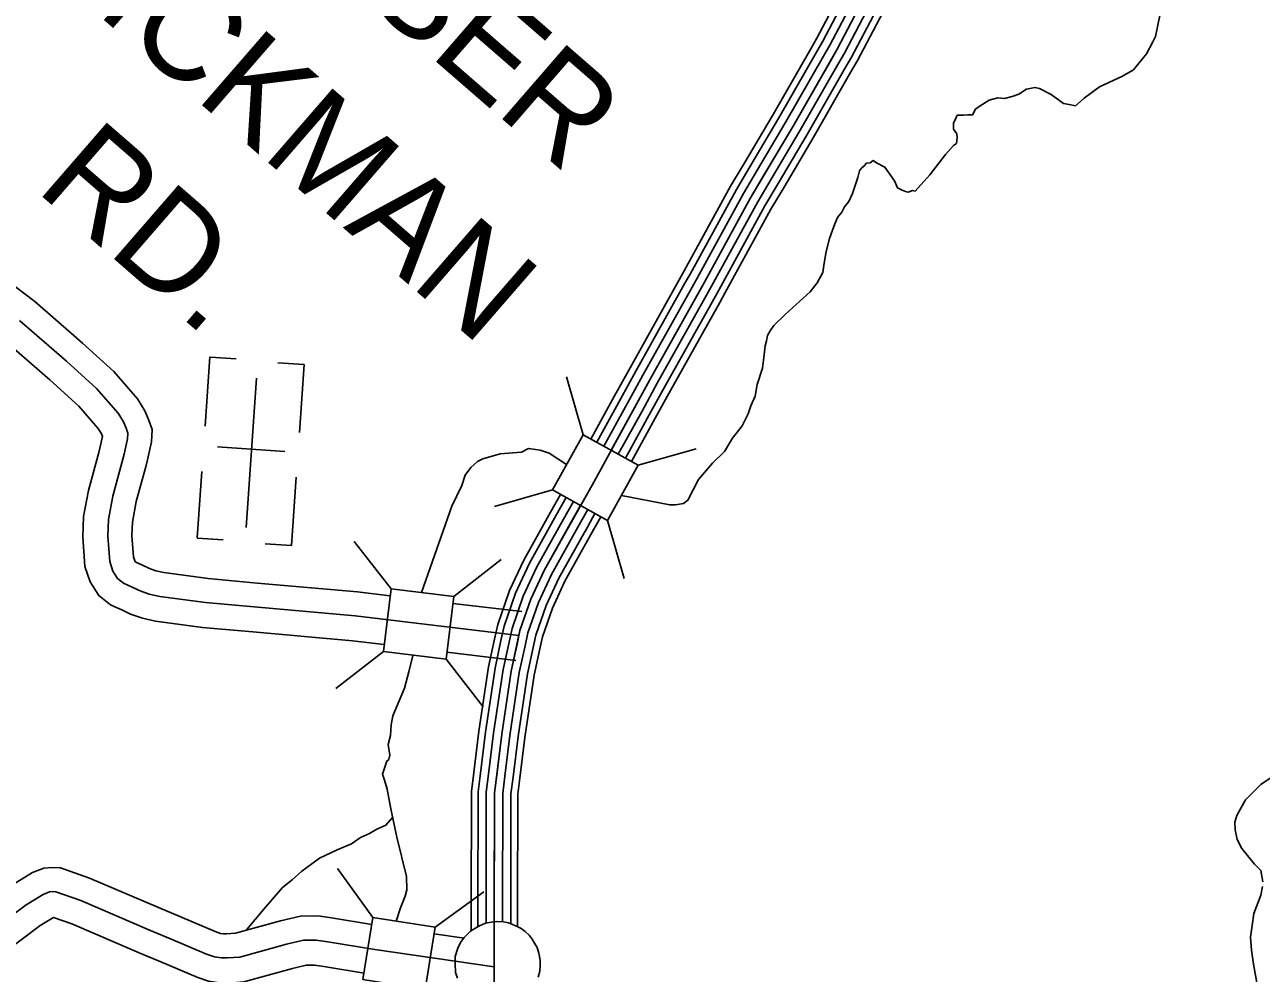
# Model space of a CAD drawing. Extents: x 1551132 to 1791609, y 378168 to 563823.
# Drawn here: x 1656295 to 1660954, y 405316 to 408888 of the extents above; entities that cross this region are included whole.
import ezdxf

# ---------------------------------------------------------------- set-up
doc = ezdxf.new("R2010")
doc.units = 0
for name, color, linetype in [('DESIGN - ROW - Right-of-Way and Easement Labels', 7, 'Continuous'), ('DESIGN - TRANSPORTATION - Text', 7, 'Continuous'), ('DESIGN - UTILITIES - Cable (Underground) with Text', 7, 'Continuous'), ('SURVEY - CENTERLINE - Preliminary Text', 7, 'Continuous'), ('SURVEY - DRAINAGE - Storm Sewer', 7, 'Continuous'), ('SURVEY - PROPERTY - Owners', 7, 'Continuous'), ('SURVEY - VEGETATION - Features with Text', 7, 'Continuous')]:
    doc.layers.add(name, color=color, linetype=linetype)

msp = doc.modelspace()

# ---------------------------------------------------------------- linework, layer by layer
at = {"layer": 'DESIGN - TRANSPORTATION - Text'}
for points in [[(1660555.903, 408843.7), (1660572.253, 408922.91), (1660572.453, 408974.97), (1660580.561, 409002.962), (1660584.686, 409036.988), (1660604.794, 409064.931), (1660624.918, 409098.881), (1660644.968, 409112.807), (1660663.009, 409124.741), (1660694.983, 409120.599), (1660714.983, 409120.507), (1660736.932, 409108.398), (1660762.882, 409098.273), (1660790.914, 409108.165), (1660824.972, 409124.032), (1660847.046, 409143.958), (1660867.121, 409165.9), (1660871.862, 409175.292)], [(1658543.482, 407114.353), (1658725.487, 407079.702), (1658746.978, 407080.086), (1658776.819, 407084.352), (1658793.868, 407097.144), (1658833.834, 407175.338), (1658886.066, 407237.173), (1658932.223, 407281.024), (1658962.406, 407330.951), (1658998.58, 407376.844), (1659020.755, 407422.803), (1659030.863, 407452.787), (1659047.004, 407488.763), (1659055.171, 407532.773), (1659075.404, 407594.758), (1659079.562, 407634.784), (1659085.728, 407678.81), (1659089.795, 407696.81), (1659093.87, 407716.811), (1659103.936, 407734.786), (1659118.011, 407754.754), (1659160.168, 407796.613), (1659216.35, 407846.423), (1659254.475, 407882.299), (1659280.599, 407916.225), (1659302.749, 407954.167), (1659306.882, 407990.193), (1659315.048, 408034.211), (1659327.231, 408082.212), (1659339.356, 408114.188), (1659347.448, 408138.181), (1659357.539, 408162.164), (1659373.614, 408182.115), (1659383.688, 408202.099), (1659399.763, 408222.049), (1659413.871, 408252.025), (1659434.104, 408312.002), (1659440.195, 408338.003), (1659448.237, 408347.978), (1659458.262, 408355.945), (1659466.303, 408365.92), (1659480.303, 408367.862), (1659492.336, 408375.82), (1659504.302, 408367.762), (1659536.227, 408351.603), (1659572.017, 408299.385), (1659583.917, 408273.301), (1659601.883, 408265.217), (1659613.858, 408259.159), (1659623.841, 408257.109), (1659639.866, 408263.051), (1659649.857, 408261.001), (1659706.081, 408322.827), (1659764.363, 408398.654), (1659794.487, 408432.564), (1659806.512, 408440.522), (1659808.595, 408462.539), (1659806.654, 408476.565), (1659794.729, 408494.632), (1659794.762, 408504.64), (1659794.821, 408518.657), (1659802.87, 408532.641), (1659808.92, 408546.633), (1659832.92, 408546.525), (1659848.919, 408548.458), (1659866.919, 408548.375), (1659877.002, 408570.359), (1659895.043, 408582.293), (1659929.118, 408604.168), (1659961.142, 408612.035), (1659987.133, 408609.927), (1660015.149, 408617.81), (1660041.182, 408625.702), (1660069.248, 408645.603), (1660101.264, 408651.469), (1660119.246, 408647.386), (1660163.145, 408625.169), (1660209.003, 408590.935), (1660230.985, 408586.834), (1660254.96, 408582.718), (1660287.067, 408610.61), (1660345.224, 408654.411), (1660431.356, 408694.079), (1660473.438, 408717.921), (1660521.662, 408777.773), (1660545.828, 408823.724), (1660555.903, 408843.7)], [(1657789.65, 406749.193), (1657904.189, 407074.943), (1657942.48, 407152.862), (1657954.63, 407190.855), (1657976.604, 407219.931), (1658000.82, 407242.715), (1658020.853, 407252.64), (1658086.91, 407272.374), (1658166.916, 407278.024), (1658192.966, 407291.933), (1658237.59, 407285.232), (1658271.689, 407274.574), (1658336.687, 407231.348)], [(1657694.377, 405512.219), (1657710.843, 405562.212), (1657729.009, 405606.18), (1657735.101, 405630.18), (1657733.292, 405680.248), (1657697.877, 405828.569), (1657674.294, 405934.788), (1657660.586, 406008.94), (1657650.719, 406043.016), (1657642.803, 406065.075), (1657658.994, 406115.06), (1657667.011, 406121.035), (1657671.077, 406137.035), (1657665.236, 406177.103), (1657673.361, 406211.112), (1657675.519, 406251.147), (1657681.644, 406285.156), (1657705.86, 406341.116), (1657726.035, 406389.084), (1657742.276, 406451.085), (1657756.492, 406507.087), (1657758.359, 406512.854)], [(1660960.817, 405660.233), (1660953.092, 405702.351), (1660929.251, 405726.56), (1660881.635, 405784.994), (1660863.861, 405819.17), (1660856.094, 405855.288), (1660854.294, 405885.347), (1660862.453, 405909.331), (1660876.619, 405935.273), (1660894.844, 405969.199), (1660953.217, 406026.876), (1661097.847, 406124.012)], [(1657130.606, 405479.551), (1657196.372, 405556.778), (1657266.903, 405638.414), (1657303.094, 405668.206), (1657339.302, 405699.999), (1657377.484, 405727.774), (1657405.625, 405749.608), (1657471.832, 405781.192), (1657525.972, 405802.843), (1657560.121, 405826.644), (1657594.229, 405842.427), (1657622.328, 405858.253), (1657656.436, 405874.037), (1657681.444, 405902.596)], [(1660961.892, 405213.496), (1660940.234, 405265.731), (1660924.784, 405349.983), (1660917.126, 405402.118), (1660913.451, 405452.227), (1660919.743, 405496.253), (1660926.034, 405540.28), (1660952.492, 405610.206), (1660958.7, 405642.216)]]:
    msp.add_lwpolyline(points, dxfattribs=at)
at = {"layer": 'DESIGN - UTILITIES - Cable (Underground) with Text'}
for p, q in [((1656992.886, 407636.503), (1656974.715, 407376.239)), ((1657092.372, 407629.554), (1656993.503, 407636.37)), ((1657348.103, 407607.641), (1657248.667, 407614.598)), ((1657330.156, 407351.56), (1657348.019, 407607.641)), ((1657275.022, 407280.807), (1657022.15, 407298.488)), ((1656962.792, 407205.776), (1656945.245, 406954.887)), ((1657300.42, 406926.067), (1657318.325, 407183.564)), ((1656945.378, 406954.837), (1657043.455, 406948.022)), ((1657300.245, 406926.117), (1657200.976, 406933.065))]:
    msp.add_line(p, q, dxfattribs=at)
msp.add_lwpolyline([(1657168.625, 407556.554), (1657129.432, 406994.924)], dxfattribs=at)
at = {"layer": 'SURVEY - CENTERLINE - Preliminary Text'}
for points in [[(1659466.329, 409231.418), (1659426.396, 409116.015), (1659280.225, 408837.474), (1659256.825, 408796.639)], [(1659489.686, 409223.334), (1659449.146, 409106.173), (1659301.891, 408825.582), (1659278.266, 408784.356)], [(1659518.986, 409213.192), (1659477.678, 409093.831), (1659329.073, 408810.665), (1659305.157, 408768.939)], [(1659548.277, 409203.059), (1659506.211, 409081.489), (1659356.256, 408795.748), (1659332.057, 408753.522)], [(1659577.568, 409192.925), (1659534.744, 409069.147), (1659383.439, 408780.831), (1659358.956, 408738.105)], [(1659606.867, 409182.783), (1659563.276, 409056.805), (1659410.621, 408765.914), (1659385.847, 408722.688)], [(1659631.166, 409174.375), (1659586.942, 409046.571), (1659433.171, 408753.538), (1659408.155, 408709.904)], [(1659506.211, 409081.489), (1659356.256, 408795.748), (1659190.251, 408506.098), (1659030.38, 408236.458), (1658856.192, 407918.791), (1658651.672, 407553.206), (1658439.002, 407165.613), (1658252.706, 406831.987), (1658201.974, 406724.051), (1658161.2, 406606.031), (1658128.225, 406453.894), (1658092.734, 406215.571), (1658065.36, 405995.24), (1658064.226, 405478.093), (1658065.043, 404950.913)], [(1659256.833, 408796.664), (1659115.337, 408549.775), (1659006.106, 408365.553)], [(1659278.275, 408784.373), (1659136.686, 408537.324), (1659027.363, 408352.953)], [(1659305.174, 408768.955), (1659163.469, 408521.716), (1659054.03, 408337.136)], [(1659332.065, 408753.538), (1659190.251, 408506.098), (1659080.696, 408321.327)], [(1659358.956, 408738.121), (1659217.034, 408490.481), (1659107.362, 408305.518)], [(1659385.855, 408722.704), (1659243.817, 408474.873), (1659134.028, 408289.701)], [(1659408.163, 408709.921), (1659266.033, 408461.914), (1659156.144, 408276.584)], [(1659006.114, 408365.561), (1658955.048, 408279.434), (1658780.336, 407960.809), (1658761.461, 407927.066)], [(1659027.372, 408352.961), (1658976.523, 408267.184), (1658801.96, 407948.834), (1658783.027, 407914.991)], [(1659054.038, 408337.144), (1659003.447, 408251.817), (1658829.076, 407933.808), (1658810.085, 407899.857)], [(1659080.704, 408321.335), (1659030.38, 408236.458), (1658856.192, 407918.791), (1658837.134, 407884.724)], [(1659107.37, 408305.526), (1659057.313, 408221.099), (1658883.308, 407903.774), (1658864.184, 407869.59)], [(1659134.036, 408289.709), (1659084.237, 408205.732), (1658910.424, 407888.749), (1658891.241, 407854.456)], [(1659156.152, 408276.601), (1659106.578, 408192.99), (1658932.924, 407876.29), (1658913.683, 407841.897)], [(1658761.469, 407927.075), (1658575.824, 407595.232), (1658517.867, 407489.613)], [(1658783.036, 407915.008), (1658597.44, 407583.257), (1658539.533, 407477.721)], [(1658810.093, 407899.866), (1658624.556, 407568.232), (1658566.715, 407462.804)], [(1658837.143, 407884.732), (1658651.672, 407553.206), (1658593.89, 407447.895)], [(1658864.192, 407869.598), (1658678.788, 407538.181), (1658621.064, 407432.987)], [(1658891.25, 407854.456), (1658705.904, 407523.156), (1658648.247, 407418.07)], [(1658913.691, 407841.906), (1658728.395, 407510.689), (1658670.788, 407405.694)], [(1658517.875, 407489.621), (1658428.752, 407327.192)], [(1658539.541, 407477.729), (1658450.368, 407315.208)], [(1658566.724, 407462.821), (1658477.484, 407300.183)], [(1658593.898, 407447.904), (1658504.6, 407285.166)], [(1658621.073, 407432.987), (1658531.725, 407270.149)], [(1658648.255, 407418.078), (1658558.841, 407255.124)], [(1658670.796, 407405.703), (1658581.332, 407242.657)], [(1658313.805, 407119.278), (1658276.505, 407052.476)], [(1658335.429, 407107.303), (1658298.08, 407040.426)], [(1658362.537, 407092.277), (1658325.146, 407025.309)], [(1658389.653, 407077.244), (1658352.212, 407010.192)], [(1658276.514, 407052.485), (1658175.516, 406871.622), (1658121.526, 406756.752), (1658077.551, 406629.457), (1658065.485, 406573.822)], [(1658298.088, 407040.434), (1658197.515, 406860.321), (1658144.458, 406747.427), (1658101.393, 406622.782), (1658089.643, 406568.58)], [(1658325.154, 407025.326), (1658225.115, 406846.154), (1658173.216, 406735.743), (1658131.292, 406614.406), (1658119.934, 406562.013)], [(1658416.76, 407062.193), (1658379.278, 406995.075)], [(1658443.868, 407047.151), (1658406.344, 406979.958)], [(1658466.359, 407034.701), (1658428.793, 406967.424)], [(1658352.22, 407010.209), (1658252.706, 406831.987), (1658201.974, 406724.051), (1658161.2, 406606.031), (1658150.233, 406555.447)], [(1658379.286, 406995.092), (1658280.297, 406817.82), (1658230.731, 406712.359), (1658191.107, 406597.656), (1658180.532, 406548.88)], [(1658406.352, 406979.983), (1658307.896, 406803.653), (1658259.489, 406700.675), (1658221.006, 406589.281), (1658210.823, 406542.313)], [(1658428.802, 406967.441), (1658330.787, 406791.895), (1658283.347, 406690.975), (1658245.814, 406582.331), (1658235.956, 406536.863)], [(1658065.493, 406573.839), (1658042.877, 406469.486), (1658006.811, 406227.305), (1657987.553, 406072.309)], [(1658089.651, 406568.597), (1658067.202, 406465.036), (1658031.302, 406223.963), (1658012.086, 406069.259)], [(1658119.942, 406562.03), (1658097.718, 406459.469), (1658062.018, 406219.763), (1658042.844, 406065.442)], [(1658150.241, 406555.463), (1658128.225, 406453.894), (1658092.734, 406215.571), (1658073.61, 406061.617)], [(1658180.541, 406548.896), (1658158.733, 406448.319), (1658123.45, 406211.379), (1658104.376, 406057.792)], [(1658210.832, 406542.33), (1658189.249, 406442.752), (1658154.166, 406207.179), (1658135.133, 406053.975)], [(1658235.964, 406536.879), (1658214.557, 406438.127), (1658179.649, 406203.704), (1658160.658, 406050.8)], [(1657987.553, 406072.325), (1657978.653, 406000.699), (1657977.695, 405562.329)], [(1658012.086, 406069.275), (1658003.37, 405999.148), (1658002.411, 405562.27)], [(1658042.844, 406065.459), (1658034.369, 405997.19), (1658033.41, 405562.204)], [(1658073.61, 406061.634), (1658065.36, 405995.24), (1658064.41, 405562.137)], [(1658104.376, 406057.808), (1658096.351, 405993.29), (1658095.409, 405562.07)], [(1658135.133, 406053.992), (1658127.35, 405991.332), (1658126.408, 405562.004)], [(1658160.658, 406050.817), (1658153.066, 405989.715), (1658152.124, 405561.945)], [(1657977.695, 405562.345), (1657977.512, 405478.118), (1657977.512, 405475.96)], [(1658002.411, 405562.287), (1658002.261, 405492.36)], [(1658033.41, 405562.22), (1658033.285, 405504.644)], [(1658064.41, 405562.154), (1658064.293, 405509.586)], [(1658095.409, 405562.087), (1658095.292, 405509.336)], [(1658126.408, 405562.02), (1658126.275, 405502.427)], [(1658152.124, 405561.962), (1658151.974, 405491.51)]]:
    msp.add_lwpolyline(points, dxfattribs=at)
at = {"layer": 'SURVEY - DRAINAGE - Storm Sewer'}
for p, q in [((1658398.956, 407343.696), (1658336.358, 407562.036)), ((1658606.784, 407228.542), (1658825.116, 407291.14)), ((1658283.794, 407135.917), (1658065.462, 407073.32)), ((1658491.564, 407020.756), (1658554.178, 406802.423)), ((1657675.772, 406763.163), (1657535.95, 406942.151)), ((1657911.614, 406734.227), (1658090.595, 406874.073)), ((1657646.827, 406527.353), (1657467.847, 406387.532)), ((1657882.612, 406498.417), (1658022.458, 406319.437)), ((1657606.881, 405526.33), (1657473.384, 405710.085)), ((1657841.566, 405489.177), (1658025.321, 405622.691))]:
    msp.add_line(p, q, dxfattribs=at)
for points in [[(1658283.794, 407135.917), (1658491.581, 407020.731), (1658606.784, 407228.542), (1658398.956, 407343.696)], [(1657646.827, 406527.353), (1657882.645, 406498.392), (1657911.614, 406734.227), (1657675.772, 406763.163)], [(1657569.72, 405291.67), (1657804.388, 405254.501), (1657841.566, 405489.177), (1657606.881, 405526.33)]]:
    msp.add_lwpolyline(points, close=True, dxfattribs=at)
at = {"layer": 'SURVEY - PROPERTY - Owners'}
for points in [[(1657672.544, 406736.784), (1657671.511, 406736.909), (1657549.072, 406751.551), (1657171.181, 406785.335), (1656986.277, 406801.861), (1656819.706, 406824.486), (1656789.207, 406830.845), (1656765.532, 406839.412), (1656738.908, 406852.104), (1656714.4, 406863.262), (1656713.017, 406864.329), (1656709.925, 406869.246), (1656704.9, 406884.538), (1656698.876, 406962.973), (1656700.817, 407014.7), (1656715.509, 407092.468), (1656752.649, 407228.472), (1656758.333, 407249.289), (1656772.866, 407317.224), (1656774.816, 407363.15), (1656761.766, 407400.81), (1656748.208, 407434.052), (1656720.534, 407479.137), (1656630.761, 407581.506), (1656512.947, 407688.659), (1656481.789, 407715.701), (1656332.976, 407844.896), (1656181.23, 407959.616)], [(1658157.175, 406587.464), (1657539.647, 406661.324), (1656976.127, 406711.692), (1656804.331, 406735.034), (1656764.399, 406743.351), (1656730.491, 406755.626), (1656700.6, 406769.876), (1656667.326, 406785.018), (1656644.843, 406802.344), (1656627.219, 406830.37), (1656615.302, 406866.646), (1656608.036, 406961.198), (1656610.428, 407024.883), (1656627.052, 407112.869), (1656670.16, 407270.74), (1656682.568, 407328.716), (1656683.459, 407349.758), (1656676.86, 407368.809), (1656667.027, 407392.918), (1656647.26, 407425.11), (1656565.937, 407517.846), (1656452.698, 407620.84), (1656275.828, 407774.386)], [(1657649.995, 406553.155), (1657649.536, 406553.213), (1657529.848, 406567.53), (1657154.715, 406601.064), (1656965.577, 406617.964), (1656788.348, 406642.048), (1656738.608, 406652.407), (1656694.067, 406668.532), (1656660.776, 406684.399), (1656635.235, 406696.024), (1656618.402, 406703.683), (1656573.978, 406737.917), (1656541.246, 406789.96), (1656522.163, 406848.053), (1656513.613, 406959.348), (1656516.472, 407035.467), (1656535.104, 407134.078), (1656574.187, 407277.198), (1656578.512, 407293.04), (1656587.945, 407337.141), (1656582.637, 407350.158), (1656571.095, 407368.95), (1656498.556, 407451.669), (1656390.066, 407550.347), (1656360.525, 407575.989), (1656216.421, 407701.092)], [(1658167.949, 406677.533), (1657908.464, 406708.567)], [(1658145.975, 406493.837), (1657885.906, 406524.946)], [(1656249.102, 405648.497), (1656324.409, 405694.856), (1656367.591, 405711.023), (1656398.09, 405713.923), (1656429.49, 405712.782), (1656539.112, 405674.481), (1656798.914, 405563.245), (1656880.071, 405528.969)], [(1656157.462, 405466.383), (1656300.192, 405573.428), (1656364.458, 405612.987), (1656388.14, 405621.854), (1656400.757, 405623.054), (1656412.515, 405622.629), (1656506.263, 405589.87), (1656763.423, 405479.767), (1656844.78, 405445.408)], [(1656880.071, 405528.969), (1657013.242, 405472.726), (1657032.809, 405465.951), (1657044.008, 405464.201), (1657056.041, 405464.109), (1657089.774, 405466.292), (1657258.57, 405513.685), (1657334.402, 405530.969), (1657399.025, 405531.694), (1657450.841, 405524.202), (1657602.562, 405499.118)], [(1656219.819, 405395.282), (1656353.3, 405495.393), (1656403.082, 405526.044), (1656472.113, 405501.918), (1656726.524, 405392.99), (1656808.097, 405358.539)], [(1656844.78, 405445.408), (1656980.726, 405387.99), (1657010.801, 405377.582), (1657036.608, 405373.548), (1657058.608, 405373.373)], [(1657058.608, 405373.373), (1657105.124, 405376.382), (1657280.928, 405425.741), (1657345.11, 405440.375), (1657393.009, 405440.908), (1657436.957, 405434.558), (1657614.712, 405405.166), (1658064.443, 405339.923)], [(1657837.631, 405464.484), (1657950.704, 405448.084)], [(1656808.097, 405358.539), (1656946.927, 405299.905), (1656987.918, 405285.721), (1657028.909, 405279.312), (1657061.283, 405279.054), (1657121.081, 405282.921), (1657304.169, 405334.322), (1657356.243, 405346.198), (1657386.759, 405346.539), (1657422.524, 405341.373), (1657573.646, 405316.38)]]:
    msp.add_lwpolyline(points, dxfattribs=at)
at = {"layer": 'SURVEY - VEGETATION - Features with Text'}
msp.add_lwpolyline([(1657925.771, 405297.355), (1657918.421, 405318.589), (1657916.863, 405351.865), (1657917.53, 405378.299), (1657926.904, 405409.758), (1657937.629, 405431.617), (1657950.462, 405449.901), (1657961.179, 405460.926), (1657974.978, 405474.218), (1657990.978, 405484.902), (1658008.944, 405495.002), (1658031.952, 405504.344), (1658054.076, 405508.552), (1658071.934, 405510.494), (1658099.05, 405509.152), (1658117.9, 405505.186), (1658133.1, 405499.819), (1658150.982, 405492.169), (1658165.615, 405484.135), (1658181.19, 405473.143), (1658195.581, 405459.384), (1658206.839, 405444.584), (1658216.289, 405428.625), (1658225.781, 405412.625), (1658232.406, 405391.941), (1658236.88, 405364.757), (1658237.547, 405345.581), (1658235.872, 405324.122), (1658230.331, 405301.255)], dxfattribs=at)

# ---------------------------------------------------------------- texts
at = {"layer": 'DESIGN - ROW - Right-of-Way and Easement Labels'}
for s, height, rotation, p in [('SMISER', 369.999, 319.044564, (1656901.031, 409567.784)), ('HICKMAN', 369.9991, 319.036486, (1656289.061, 409169.731)), ('RD.', 369.9991, 319.036486, (1656331.26, 408266.182))]:
    msp.add_text(s, height=height, rotation=rotation, dxfattribs=at).set_placement(p)

doc.saveas('drawing.dxf')
